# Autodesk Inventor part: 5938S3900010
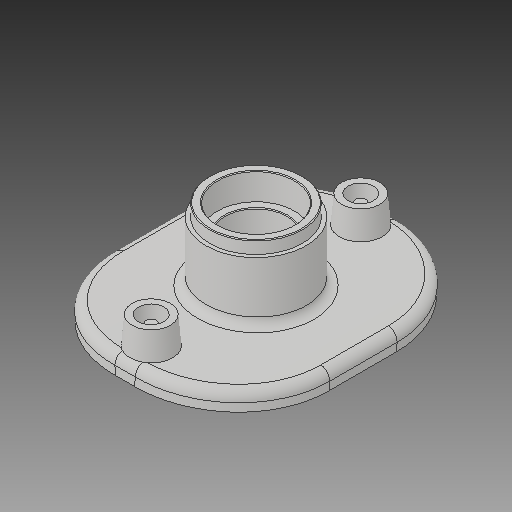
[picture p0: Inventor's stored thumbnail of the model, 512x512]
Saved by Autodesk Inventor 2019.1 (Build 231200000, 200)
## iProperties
Created: 2017-08
Part Number: 5938S3900010
Material: Generic
Description: PLASSON SENSOR ADAPTOR WITH STAINLESS STEEL THREAD 18''48''IPSx1''
Document SubType Name: Modeling
Designer: Кирилл
Density: 1 g/cm^3
Appearance: Default
Author: Кирилл
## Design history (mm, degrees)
derived "5938S.ipt"
feature "Solid1::5938S.ipt"
feature "Solid2::5938S.ipt"
feature "Solid3::5938S.ipt"
tag "TaggingFeature1"
body "Solid1"
other parameters: "d0" = 1213.7, "d1" = 84.836, "d3" = 102.87, "d4" = 0, "d5" = 38.1762, "d11" = 788.905, "d38" = 3.6411, "d40" = 624.376, "d41" = 15, "d42" = 41.148, "d46" = 5 deg, "d47" = 4, "d51" = 14, "d52" = 0, "d53" = 3, "d54" = 0, "d75" = 0, "d77" = 0, "d78" = 0.30291, "d82" = 35.052, "d83" = 39.3783, "d84" = 36.3492, "d85" = 24.2328, "d86" = 30.291, "d89" = 10.5156, "d90" = 4.90728, "d95" = 3.175, "d97" = 360 deg, "d99" = 7.0104, "d_" = 1213.7, "B_" = 84.836, "H_" = 35.052, "L_" = 102.87, "G_" = 30.291
